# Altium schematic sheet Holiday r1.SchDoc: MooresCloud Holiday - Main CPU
size A3; DrawnBy: KJM; Organization: Kean Electronics for MooresCloud; Revision: 1; SheetNumber: 1; SheetTotal: 2
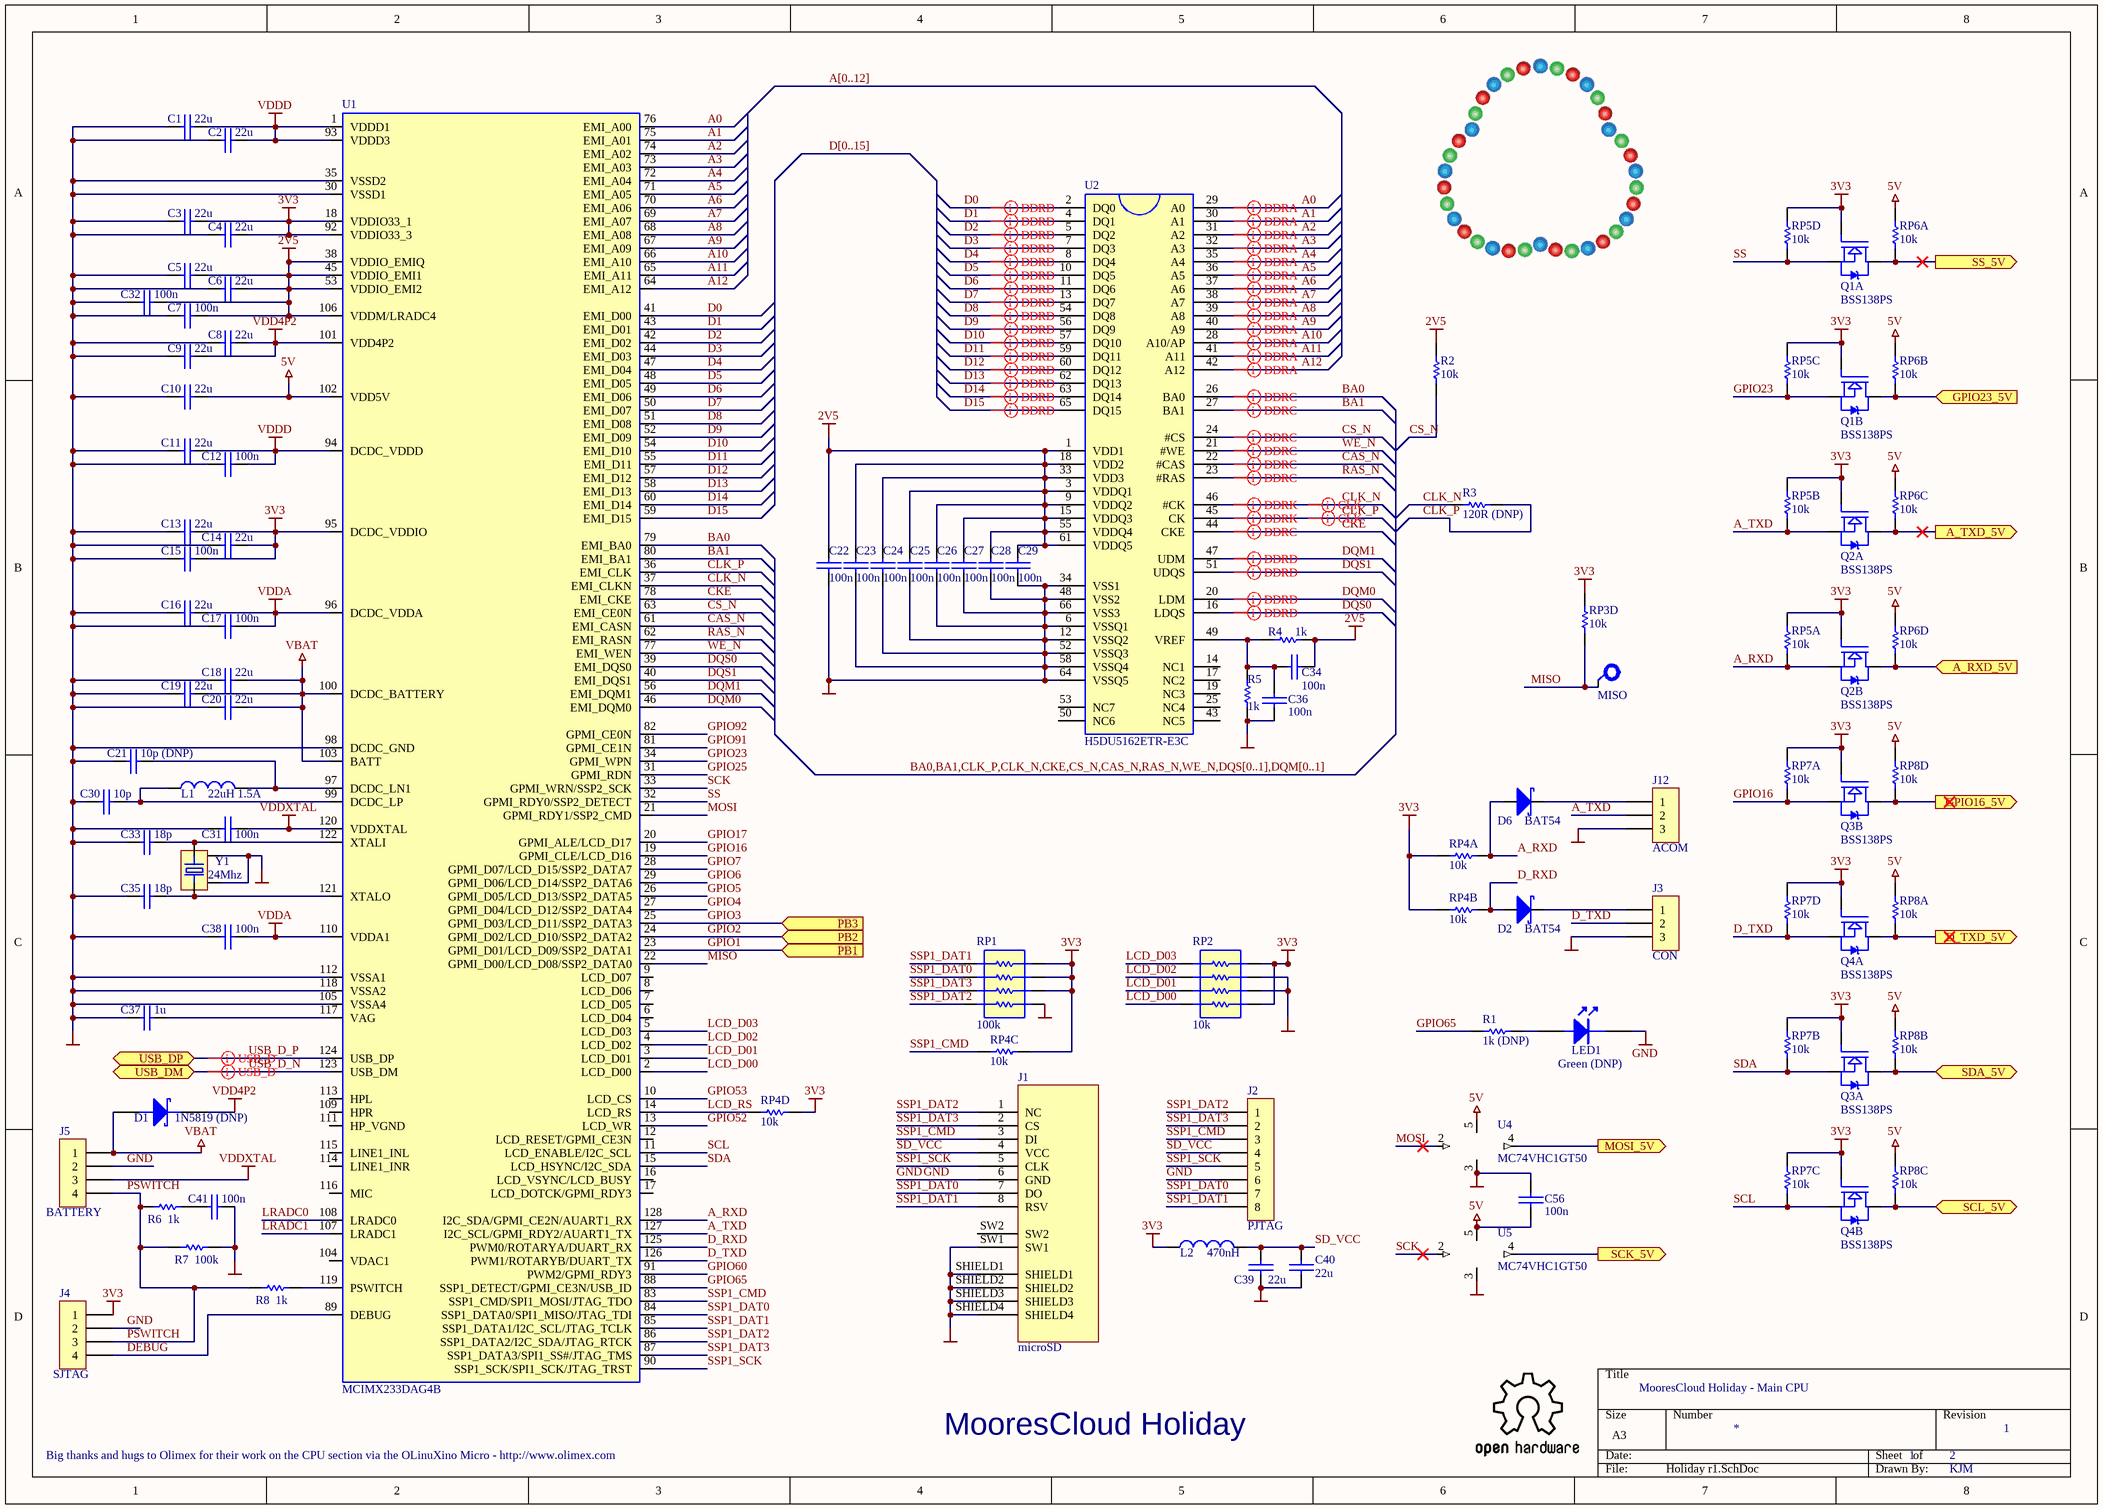
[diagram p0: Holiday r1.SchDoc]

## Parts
C1  22u  [ARA_0603]
C2  22u  [ARA_0603]
C3  22u  [ARA_0603]
C4  22u  [ARA_0603]
C5  22u  [ARA_0603]
C6  22u  [ARA_0603]
C7  100n  [ARA_0603]
C8  22u  [ARA_0603]
C9  22u  [ARA_0603]
C10  22u  [ARA_0603]
C11  22u  [ARA_0603]
C12  100n  [ARA_0603]
C13  22u  [ARA_0603]
C14  22u  [ARA_0603]
C15  100n  [ARA_0603]
C16  22u  [ARA_0603]
C17  100n  [ARA_0603]
C18  22u  [ARA_0603]
C19  22u  [ARA_0603]
C20  22u  [ARA_0603]
C21  10p (DNP)  [ARA_0603]
C22  100n  [ARA_0603]
C23  100n  [ARA_0603]
C24  100n  [ARA_0603]
C25  100n  [ARA_0603]
C26  100n  [ARA_0603]
C27  100n  [ARA_0603]
C28  100n  [ARA_0603]
C29  100n  [ARA_0603]
C30  10p  [ARA_0603]
C31  100n  [ARA_0603]
C32  100n  [ARA_0603]
C33  18p  [ARA_0603]
C34  100n  [ARA_0603]
C35  18p  [ARA_0603]
C36  100n  [ARA_0603]
C37  1u  [ARA_0603]
C38  100n  [ARA_0603]
C39  22u  [ARA_0603]
C40  22u  [ARA_0603]
C41  100n  [ARA_0603]
C56  100n  [ARA_0603]
D1  1N5819 (DNP)  [SOD-123]
D2  BAT54  [ARA_SOT-23]
D6  BAT54  [ARA_SOT-23]
J1  microSD  [MICROSD-47309-3751 WITH CARD]
J2  PJTAG  [53047-08]  (no BOM)
J3  CON  [HDR1X3]  (no BOM)
J4  SJTAG  [HDR1X4]  (no BOM)
J5  BATTERY  [HDR1X4]  (no BOM)
J12  ACOM  [HDR1X3]  (no BOM)
L1  22uH 1.5A  [RCL_L7078]
L2  470nH  [ARA_0805]
LED1  Green (DNP)  [LED_0805]
Q1  BSS138PS  [ARA_SOT-363]  (parts A,B of 2)
Q2  BSS138PS  [ARA_SOT-363]  (parts A,B of 2)
Q3  BSS138PS  [ARA_SOT-363]  (parts A,B of 2)
Q4  BSS138PS  [ARA_SOT-363]  (parts A,B of 2)
R1  1k (DNP)  [ARA_0603]
R2  10k  [ARA_0603]
R3  120R (DNP)  [ARA_0603]
R4  1k  [ARA_0603]
R5  1k  [ARA_0603]
R6  1k  [ARA_0603]
R7  100k  [ARA_0603]
R8  1k  [ARA_0603]
RP1  100k  [RESPACK_0603x4]
RP2  10k  [RESPACK_0603x4]
RP3  10k  [RESPACK_0603x4]  (part D of 4)
RP4  10k  [RESPACK_0603x4]  (parts A,B,C,D of 4)
RP5  10k  [RESPACK_0603x4]  (parts A,B,C,D of 4)
RP6  10k  [RESPACK_0603x4]  (parts A,B,C,D of 4)
RP7  10k  [RESPACK_0603x4]  (parts A,B,C,D of 4)
RP8  10k  [RESPACK_0603x4]  (parts A,B,C,D of 4)
TP1  MISO  [SMD_TESTTERMINAL]  (no BOM)
U1  MCIMX233DAG4B  [LQFP128]
U2  H5DU5162ETR-E3C  [TSOP-II-66]
U4  MC74VHC1GT50  [ARA_SOT-23-5L]
U5  MC74VHC1GT50  [ARA_SOT-23-5L]
Y1  24Mhz  [CRYSTAL_ABMM2]

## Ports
A_RXD_5V (in), A_TXD_5V (out), D_TXD_5V (out), GPIO16_5V (out), GPIO23_5V (in), MOSI_5V (out), PB1 (in), PB2 (in), PB3 (in), SCK_5V (out), SCL_5V (bidir), SDA_5V (bidir), SS_5V (out), USB_DM (bidir), USB_DP (bidir)

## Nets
2V5: C5.1 C6.1 C7.1 C22.1 C23.1 C24.1 C25.1 C26.1 C27.1 C28.1 C29.1 C32.1 C34.1 R2.2 R4.2 U1.38(VDDIO_EMIQ) U1.45(VDDIO_EMI1) U1.53(VDDIO_EMI2) U1.106(VDDM/LRADC4) U2.1(VDD1) U2.3(VDDQ1) U2.9(VDDQ2) U2.15(VDDQ3) U2.18(VDD2) U2.33(VDD3) U2.55(VDDQ4) U2.61(VDDQ5)
3V3: C3.1 C4.1 C13.1 C14.1 C15.1 J4.1 L2.2 Q1.2(G1) Q1.5(G2) Q2.2(G1) Q2.5(G2) Q3.2(G1) Q3.5(G2) Q4.2(G1) Q4.5(G2) RP1.1.2 RP1.2.2 RP1.3.2 RP2.1.2 RP2.4.2 RP3.4.2 RP4.1.2 RP4.2.2 RP4.3.2 RP4.4.2 RP5.1.2 RP5.2.2 RP5.3.2 RP5.4.2 RP7.1.2 RP7.2.2 RP7.3.2 RP7.4.2 U1.18(VDDIO33_1) U1.92(VDDIO33_3) U1.95(DCDC_VDDIO)
5V: C10.1 C56.2 RP6.1.2 RP6.2.2 RP6.3.2 RP6.4.2 RP8.1.2 RP8.2.2 RP8.3.2 RP8.4.2 U1.102(VDD5V) U4.5(VCC) U5.5(VCC)
GND: C1.2 C2.2 C3.2 C4.2 C5.2 C6.2 C7.2 C8.2 C9.2 C10.2 C11.2 C12.2 C13.2 C14.2 C15.2 C16.2 C17.2 C18.2 C19.2 C20.2 C21.2 C22.2 C23.2 C24.2 C25.2 C26.2 C27.2 C28.2 C29.2 C30.2 C31.2 C32.2 C33.2 C35.2 C36.2 C37.2 C38.2 C39.2 C40.2 C41.2 C56.1 J1.6(GND) J1.SHIELD1 J1.SHIELD2 J1.SHIELD3 J1.SHIELD4 J1.SW1 J2.6 J3.3 J4.2 J5.2 J12.3 LED1.K R5.2 R7.1 RP1.4.2 RP2.2.2 RP2.3.2 U1.30(VSSD1) U1.35(VSSD2) U1.98(DCDC_GND) U1.105(VSSA4) U1.112(VSSA1) U1.118(VSSA2) U2.6(VSSQ1) U2.12(VSSQ2) U2.34(VSS1) U2.48(VSS2) U2.52(VSSQ3) U2.58(VSSQ4) U2.64(VSSQ5) U2.66(VSS3) U4.3(GND) U5.3(GND) Y1.3 Y1.4
VBAT: C18.1 C19.1 C20.1 D1.1(A) J5.1 U1.100(DCDC_BATTERY) U1.103(BATT)
VDD4P2: C8.1 C9.1 D1.2(K) U1.101(VDD4P2)
VDDA: C16.1 C17.1 C38.1 U1.96(DCDC_VDDA) U1.110(VDDA1)
VDDD: C1.1 C2.1 C11.1 C12.1 U1.1(VDDD1) U1.93(VDDD3) U1.94(DCDC_VDDD)
VDDXTAL: C31.1 J5.3 U1.120(VDDXTAL)
A0: U1.76(EMI_A00) U2.29(A0)
A1: U1.75(EMI_A01) U2.30(A1)
A2: U1.74(EMI_A02) U2.31(A2)
A3: U1.73(EMI_A03) U2.32(A3)
A4: U1.72(EMI_A04) U2.35(A4)
A5: U1.71(EMI_A05) U2.36(A5)
A6: U1.70(EMI_A06) U2.37(A6)
A7: U1.69(EMI_A07) U2.38(A7)
A8: U1.68(EMI_A08) U2.39(A8)
A9: U1.67(EMI_A09) U2.40(A9)
A10: U1.66(EMI_A10) U2.28(A10/AP)
A11: U1.65(EMI_A11) U2.41(A11)
A12: U1.64(EMI_A12) U2.42(A12)
A_RXD: D6.1(A) Q2.4(S2) RP4.1.1 RP5.1.1 U1.128(I2C_SDA/GPMI_CE2N/AUART1_RX)
A_RXD_5V: Q2.3(D2) RP6.4.1 ; port A_RXD_5V
A_TXD: J12.2 Q2.1(S1) RP5.2.1 U1.127(I2C_SCL/GPMI_RDY2/AUART1_TX)
A_TXD_5V: Q2.6(D1) RP6.3.1 ; port A_TXD_5V
BA0: U1.79(EMI_BA0) U2.26(BA0)
BA1: U1.80(EMI_BA1) U2.27(BA1)
CAS_N: U1.61(EMI_CASN) U2.22(#CAS)
CKE: U1.78(EMI_CKE) U2.44(CKE)
CLK_N: R3.1 U1.37(EMI_CLKN) U2.46(#CK)
CLK_P: R3.2 U1.36(EMI_CLK) U2.45(CK)
CS_N: R2.1 U1.63(EMI_CE0N) U2.24(#CS)
D0: U1.41(EMI_D00) U2.2(DQ0)
D1: U1.43(EMI_D01) U2.4(DQ1)
D2: U1.42(EMI_D02) U2.5(DQ2)
D3: U1.44(EMI_D03) U2.7(DQ3)
D4: U1.47(EMI_D04) U2.8(DQ4)
D5: U1.48(EMI_D05) U2.10(DQ5)
D6: U1.49(EMI_D06) U2.11(DQ6)
D7: U1.50(EMI_D07) U2.13(DQ7)
D8: U1.51(EMI_D08) U2.54(DQ8)
D9: U1.52(EMI_D09) U2.56(DQ9)
D10: U1.54(EMI_D10) U2.57(DQ10)
D11: U1.55(EMI_D11) U2.59(DQ11)
D12: U1.57(EMI_D12) U2.60(DQ12)
D13: U1.58(EMI_D13) U2.62(DQ13)
D14: U1.60(EMI_D14) U2.63(DQ14)
D15: U1.59(EMI_D15) U2.65(DQ15)
D_RXD: D2.1(A) RP4.2.1 U1.125(PWM0/ROTARYA/DUART_RX)
D_TXD: J3.2 Q4.1(S1) RP7.4.1 U1.126(PWM1/ROTARYB/DUART_TX)
D_TXD_5V: Q4.6(D1) RP8.1.1 ; port D_TXD_5V
DEBUG: J4.4 U1.89(DEBUG)
DQM0: U1.46(EMI_DQM0) U2.20(LDM)
DQM1: U1.56(EMI_DQM1) U2.47(UDM)
DQS0: U1.39(EMI_DQS0) U2.16(LDQS)
DQS1: U1.40(EMI_DQS1) U2.51(UDQS)
GPIO1: U1.23(GPMI_D01/LCD_D09/SSP2_DATA1) ; port PB1
GPIO2: U1.24(GPMI_D02/LCD_D10/SSP2_DATA2) ; port PB2
GPIO3: U1.25(GPMI_D03/LCD_D11/SSP2_DATA3) ; port PB3
GPIO4: U1.27(GPMI_D04/LCD_D12/SSP2_DATA4)
GPIO5: U1.26(GPMI_D05/LCD_D13/SSP2_DATA5)
GPIO6: U1.29(GPMI_D06/LCD_D14/SSP2_DATA6)
GPIO7: U1.28(GPMI_D07/LCD_D15/SSP2_DATA7)
GPIO16: Q3.4(S2) RP7.1.1 U1.19(GPMI_CLE/LCD_D16)
GPIO16_5V: Q3.3(D2) RP8.4.1 ; port GPIO16_5V
GPIO17: U1.20(GPMI_ALE/LCD_D17)
GPIO23: Q1.4(S2) RP5.3.1 U1.34(GPMI_WPN)
GPIO23_5V: Q1.3(D2) RP6.2.1 ; port GPIO23_5V
GPIO25: U1.31(GPMI_RDN)
GPIO52: U1.13(LCD_WR)
GPIO53: U1.10(LCD_CS)
GPIO60: U1.91(PWM2/GPMI_RDY3)
GPIO65: R1.2 U1.88(SSP1_DETECT/GPMI_CE3N/USB_ID)
GPIO91: U1.81(GPMI_CE1N)
GPIO92: U1.82(GPMI_CE0N)
LCD_D00: RP2.4.1 U1.2(LCD_D00)
LCD_D01: RP2.3.1 U1.3(LCD_D01)
LCD_D02: RP2.2.1 U1.4(LCD_D02)
LCD_D03: RP2.1.1 U1.5(LCD_D03)
LCD_RS: RP4.4.1 U1.14(LCD_RS)
LRADC0: U1.108(LRADC0)
LRADC1: U1.107(LRADC1)
MISO: RP3.4.1 TP1.1 U1.22(GPMI_D00/LCD_D08/SSP2_DATA0)
MOSI: U1.21(GPMI_RDY1/SSP2_CMD) U4.2(IN)
MOSI_5V: U4.4(OUT) ; port MOSI_5V
PSWITCH: J4.3 J5.4 R6.2 R7.2 R8.2
RAS_N: U1.62(EMI_RASN) U2.23(#RAS)
SCK: U1.33(GPMI_WRN/SSP2_SCK) U5.2(IN)
SCK_5V: U5.4(OUT) ; port SCK_5V
SCL: Q4.4(S2) RP7.3.1 U1.11(LCD_ENABLE/I2C_SCL)
SCL_5V: Q4.3(D2) RP8.3.1 ; port SCL_5V
SD_VCC: C39.1 C40.1 J1.4(VCC) J2.4 L2.1
SDA: Q3.1(S1) RP7.2.1 U1.15(LCD_HSYNC/I2C_SDA)
SDA_5V: Q3.6(D1) RP8.2.1 ; port SDA_5V
SS: Q1.1(S1) RP5.4.1 U1.32(GPMI_RDY0/SSP2_DETECT)
SS_5V: Q1.6(D1) RP6.1.1 ; port SS_5V
SSP1_CMD: J1.3(DI) J2.3 RP4.3.1 U1.83(SSP1_CMD/SPI1_MOSI/JTAG_TDO)
SSP1_DAT0: J1.7(DO) J2.7 RP1.2.1 U1.84(SSP1_DATA0/SPI1_MISO/JTAG_TDI)
SSP1_DAT1: J1.8(RSV) J2.8 RP1.1.1 U1.85(SSP1_DATA1/I2C_SCL/JTAG_TCLK)
SSP1_DAT2: J1.1(NC) J2.1 RP1.4.1 U1.86(SSP1_DATA2/I2C_SDA/JTAG_RTCK)
SSP1_DAT3: J1.2(CS) J2.2 RP1.3.1 U1.87(SSP1_DATA3/SPI1_SS#/JTAG_TMS)
SSP1_SCK: J1.5(CLK) J2.5 U1.90(SSP1_SCK/SPI1_SCK/JTAG_TRST)
USB_D_N: U1.123(USB_DM) ; port USB_DM
USB_D_P: U1.124(USB_DP) ; port USB_DP
WE_N: U1.77(EMI_WEN) U2.21(#WE)
NetC21_1: C21.1 L1.1 U1.97(DCDC_LN1)
NetC30_1: C30.1 L1.2 U1.99(DCDC_LP)
NetC33_1: C33.1 U1.122(XTALI) Y1.2
NetC34_2: C34.2 C36.1 R4.1 R5.1 U2.49(VREF)
NetC35_1: C35.1 U1.121(XTALO) Y1.1
NetC37_1: C37.1 U1.117(VAG)
NetC41_1: C41.1 R6.1
NetD2_2: D2.2(K) J3.1
NetD6_2: D6.2(K) J12.1
NetLED1_A: LED1.A R1.1
NetR8_1: R8.1 U1.119(PSWITCH)

Not connected (* = marked no-connect by the designer): J1 SW2; U1 6(LCD_D04) 7(LCD_D05) 8(LCD_D06) 9(LCD_D07) 12(LCD_RESET/GPMI_CE3N) 16(LCD_VSYNC/LCD_BUSY) 17(LCD_DOTCK/GPMI_RDY3) 104(VDAC1) 109(HPR) 111(HP_VGND) 113(HPL) 114(LINE1_INR) 115(LINE1_INL) 116(MIC); U2 14(NC1) 17(NC2) 19(NC3) 25(NC4) 43(NC5) 50(NC6) 53(NC7); U4 1; U5 1

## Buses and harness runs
bus A[0..12]
bus BA0,BA1,CLK_P,CLK_N,CKE,CS_N,CAS_N,RAS_N,WE_N,DQS[0..1],DQM[0..1]
bus D[0..15]

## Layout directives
net class DDR_DATA: D0, D1, D2, D3, D4, D5, D6, D7, D8, D9, D10, D11, D12, D13, D14, D15, DQM0, DQM1, DQS0, DQS1
net class DDR_ADDR: A0, A1, A2, A3, A4, A5, A6, A7, A8, A9, A10, A11, A12
net class DDR_CLK: CLK_N, CLK_P
differential pair: CLK_N, CLK_P, USB_D_N, USB_D_P
net class DDR_CTL: BA0, BA1, CAS_N, CKE, CS_N, RAS_N, WE_N

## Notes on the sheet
- Big thanks and hugs to Olimex for their work on the CPU section via the OLinuXino Micro - http://www.olimex.com
- MooresCloud Holiday

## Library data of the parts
C1-C6 C8-C11 C13 C14 C16 C18-C20 C39 C40 = CAP: Capacitor; 1.Manufacturer: TDK; 2.MfgNo: C1608X5R0J226M080AC; 4.CatNo: 445-8028-1-ND; 9.UnitCost: 0.0816
C7 C12 C15 C17 C22-C29 C31 C32 C34 C36 C38 C41 C56 = CAP: Capacitor; 1.Manufacturer: Yageo; 4.CatNo: 311-1343-2-ND; 2.MfgNo: CC0603ZRY5V9BB104; 9.UnitCost: 0.0034
C21 C30 = CAP: Capacitor; 1.Manufacturer: Murata; 4.CatNo: 490-1403-1-ND; 2.MfgNo: GRM1885C1H100JA01D; 9.UnitCost: 0.008
C33 C35 = CAP: Capacitor; 1.Manufacturer: Murata; 2.MfgNo: GRM1885C1H180JA01D; 4.CatNo: 490-1409-2-ND; 9.UnitCost: 0.008
C37 = CAP: Capacitor; 1.Manufacturer: Yageo; 4.CatNo: 311-1372-2-ND; 2.MfgNo: CC0603ZRY5V7BB105; 9.UnitCost: 0.0083
D1 = DIODE SCHOTTKY: Schottky Diode 1N5819HW (DNP); 1.Manufacturer: Diodes Inc; 2.MfgNo: 1N5819HW-7-F; 4.CatNo: 1N5819HW-FDITR-ND; 9.UnitCost: 0.08
D2 D6 = BAT54: Schottky Diode; pin to pad: 2>3; 1.Manufacturer: Fairchild; 4.CatNo: BAT54FSTR-ND; 9.UnitCost: 0.027
J1 = microSD: microSD Socket Push/Pull; pin to pad: SHIELD1>G1 SHIELD2>G1 SHIELD3>G2 SHIELD4>G2 SW1>G3 SW2>G4; 1.Manufacturer: Molex; 2.MfgNo: 473093751; 4.CatNo: WM3974TR-ND; 9.UnitCost: 0.90
J2 = CON8: Connector; 1.Manufacturer: DNP; 9.UnitCost: 0
J3 J12 = CON3: Connector; 1.Manufacturer: DNP; 9.UnitCost: 0
J4 J5 = CON4: Connector; 1.Manufacturer: DNP; 9.UnitCost: 0
L1 = Inductor: 1.Manufacturer: Taiyo Yuden; 2.MfgNo: NR6045T220M; 4.CatNo: 587-2082-1-ND; 9.UnitCost: 0.12
L2 = Inductor: Ferrite; 1.Manufacturer: Abracon; 2.MfgNo: AISC-0805-R47J-T; 4.CatNo: 535-10509-1-ND; 9.UnitCost: 0.10
LED1 = LED: 1.Manufacturer: Kingbright; 4.CatNo: 754-1131-1-ND; 9.UnitCost: 0.0611; 2.MfgNo: APT2012SGC
Q1-Q4 = BSS138PS: Dual N Channel MOSFET; 1.Manufacturer: NXP; 4.CatNo: 568-8393-2-ND; 2.MfgNo: BSS138PS,115; 9.UnitCost: 0.07
R1 R4-R6 R8 = Res Semi: Resistor; 1.Manufacturer: Yageo; 4.CatNo: 311-1.00KHRTR-ND; 2.MfgNo: RC0603FR-071KL; 9.UnitCost: 0.0017
R2 = Res Semi: Resistor; 1.Manufacturer: Yageo; 9.UnitCost: 0.0017; 4.CatNo: 311-10.0KHRTR-ND; 2.MfgNo: RC0603FR-0710KL
R3 = Res Semi: Resistor; 1.Manufacturer: Yageo; 4.CatNo: 311-120HRTR-ND; 2.MfgNo: RC0603FR-07120RL; 9.UnitCost: 0.0017
R7 = Res Semi: Resistor; 1.Manufacturer: Yageo; 4.CatNo: 311-100KHRTR-ND; 2.MfgNo: RC0603FR-07100KL; 9.UnitCost: 0.0017
RP1 = RESISTOR_PACK_4_1206: Resistor Pack 4x0603; 1.Manufacturer: Vishay Dale; 2.MfgNo: CRA06S083100KJTA; 4.CatNo: CRA6S8100KTR-ND; 9.UnitCost: 0.009
RP2 = RESISTOR_PACK_4_1206: Resistor Pack 4x0603; 1.Manufacturer: Vishay Dale; 2.MfgNo: CRA06S08310K0JTA; 4.CatNo: CRA6S810KTR-ND; 9.UnitCost: 0.009
RP3-RP8 = RESISTOR_PACK_4_1206_SPLIT: Resistor Pack 4x0603; 1.Manufacturer: Vishay Dale; 2.MfgNo: CRA06S08310K0JTA; 4.CatNo: CRA6S810KTR-ND; 9.UnitCost: 0.009
TP1 = TESTTERMINAL: Test Point
U1 = MCIMX233DAG4B: Freescale i.MX233 128 pin LQFP package; 2.MfgNo: MCIMX233DAG4C; 4.CatNo: MCIMX233DAG4C-ND; 9.UnitCost: 4.880
U2 = H5DU5162ETR-E3C: SDRAM DDR400 66TSOP-II; 1.Manufacturer: Hynix; 9.UnitCost: 2.240
U4 U5 = MC74VHC1GT50: CMOS Logic Level Shifter; 1.Manufacturer: On Semi; 2.MfgNo: M74VHC1GT50DTT1G; 4.CatNo: M74VHC1GT50DTT1GOSTR-ND; 9.UnitCost: 0.07
Y1 = CRYSTAL_ABMM2: ABMM2 SMD Crystal; 1.Manufacturer: Abracon; 2.MfgNo: ABMM2-24.000MHZ-E2-T; 4.CatNo: 535-9638-2-ND; 9.UnitCost: 0.48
